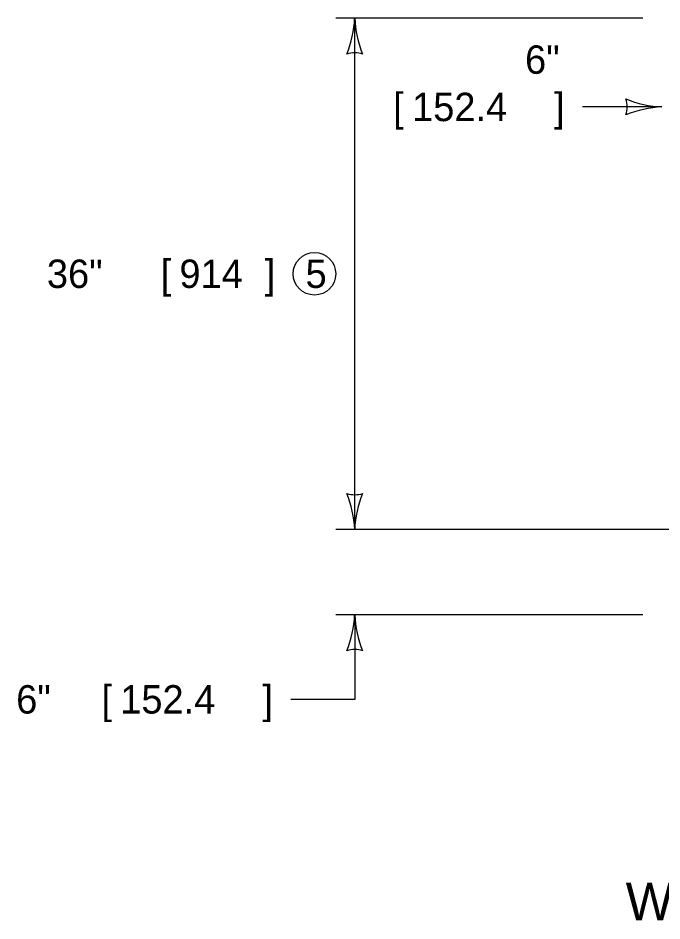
# Model space of a CAD drawing. Extents: x 49991.4 to 50041.6, y 49987.6 to 50011.4.
# Drawn here: x 50036.979 to 50038.338, y 49991.53 to 49993.437 of the extents above; entities that cross this region are included whole.
import ezdxf

# ---------------------------------------------------------------- set-up
doc = ezdxf.new("R2010")
doc.units = 0
doc.layers.add('Level 2', color=7, linetype='Continuous')
doc.layers.add('Level 3', color=7, linetype='Continuous')

msp = doc.modelspace()

# ---------------------------------------------------------------- linework, layer by layer
at = {"layer": 'Level 2'}
msp.add_circle((50037.6045, 49992.8968), 0.045, dxfattribs=at)
at = {"layer": 'Level 3'}
for p, q in [((50038.2979, 49993.4368), (50037.6495, 49993.4368)), ((50037.6895, 49992.3568), (50037.6895, 49993.4368)), ((50038.3379, 49993.2491), (50038.1703, 49993.2491)), ((50038.4779, 49992.3568), (50037.6495, 49992.3568)), ((50038.2979, 49992.1768), (50037.6495, 49992.1768))]:
    msp.add_line(p, q, dxfattribs=at)
msp.add_lwpolyline([(50037.6895, 49992.1768), (50037.6895, 49991.9981), (50037.5546, 49991.9981)], dxfattribs=at)
for centre, radius, start, end in [((50037.4673, 49993.4459), 0.2223, 337.456, 357.6395), ((50037.4673, 49993.4459), 0.2223, 337.456, 357.6395), ((50037.9222, 49993.4483), 0.233, 182.8273, 202.0772), ((50037.9222, 49993.4483), 0.233, 182.8273, 202.0772), ((50037.6895, 49993.3085), 0.0548, 72.1388, 107.8612), ((50037.6895, 49993.3085), 0.0548, 72.1388, 107.8612), ((50038.347, 49993.4713), 0.2223, 247.456, 267.6395), ((50038.2096, 49993.2491), 0.0548, 342.1388, 17.8612), ((50038.3494, 49993.0164), 0.233, 92.8273, 112.0772), ((50037.6895, 49992.485), 0.0548, 252.1388, 287.8612), ((50037.4568, 49992.3453), 0.233, 2.8273, 22.0772), ((50037.9116, 49992.3476), 0.2223, 157.456, 177.6395), ((50037.4673, 49992.1859), 0.2223, 337.456, 357.6395), ((50037.9222, 49992.1883), 0.233, 182.8273, 202.0772), ((50037.6895, 49992.0485), 0.0548, 72.1388, 107.8612)]:
    msp.add_arc(centre, radius, start, end, dxfattribs=at)

# ---------------------------------------------------------------- texts
at = {"layer": 'Level 2'}
for s, p in [('6"', (50038.049, 49993.3191)), ('[', (50037.7708, 49993.2191)), ('152.4', (50037.8105, 49993.2191)), (']', (50038.1105, 49993.2191)), ('36" ', (50037.0399, 49992.8668)), ('[', (50037.2799, 49992.8668)), ('914', (50037.3196, 49992.8668)), (']', (50037.4996, 49992.8668)), ('6" ', (50036.9751, 49991.9681)), ('[', (50037.1551, 49991.9681)), ('152.4', (50037.1947, 49991.9681)), (']', (50037.4947, 49991.9681))]:
    msp.add_text(s, height=0.06, rotation=360, dxfattribs=at).set_placement(p)
for s, height, p in [('5', 0.06, (50037.5858, 49992.8668)), ('WITH FRAME AND GRATE', 0.08, (50038.2613, 49991.5313))]:
    msp.add_text(s, height=height, dxfattribs=at).set_placement(p)

doc.saveas('drawing.dxf')
